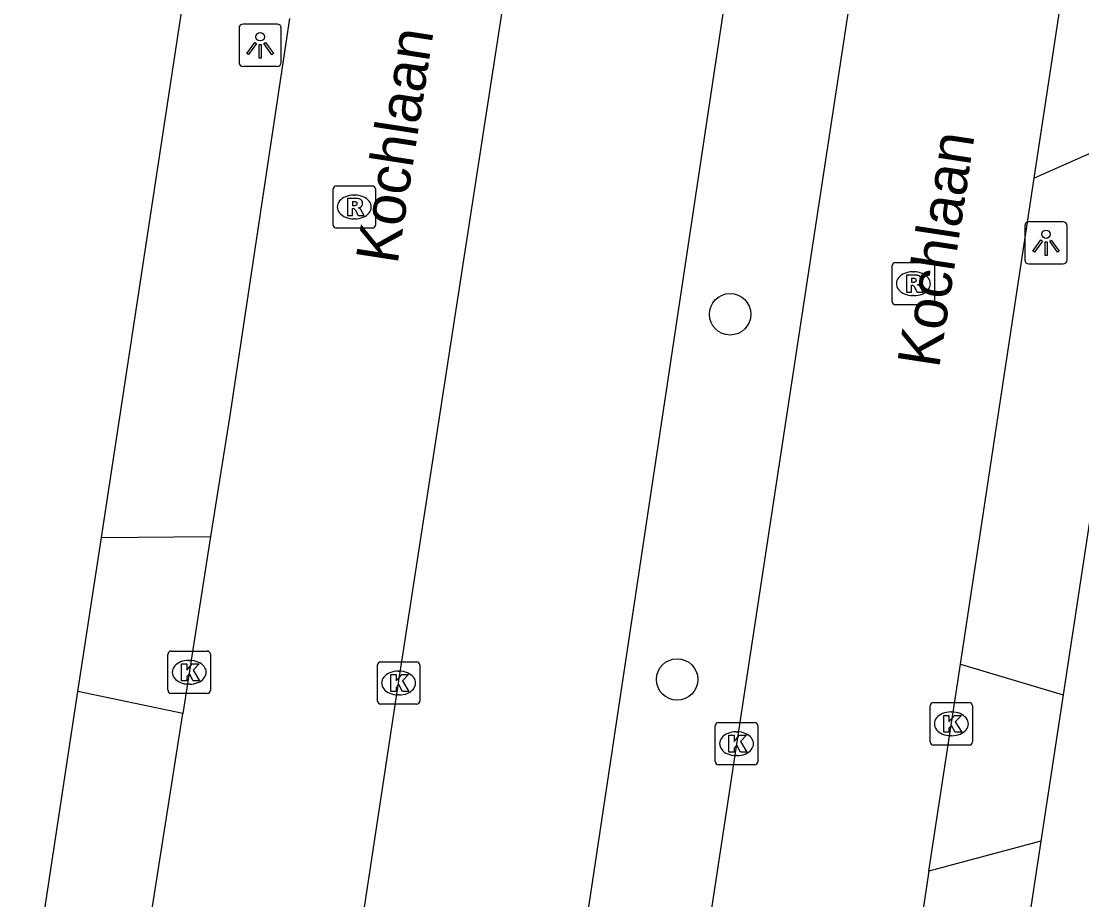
# Model space of a CAD drawing. Extents: x 161486 to 162249, y 379484 to 380829.
# Drawn here: x 161895.53 to 161920.56, y 380438.28 to 380459.01 of the extents above; entities that cross this region are included whole.
import ezdxf

# ---------------------------------------------------------------- set-up
doc = ezdxf.new("R2010")
doc.units = 0
for name, color, linetype in [('IMGEO_Boom', 7, 'Continuous'), ('IMGEO_Groenvoorziening', 7, 'Continuous'), ('IMGEO_Kolk', 7, 'Continuous'), ('IMGEO_Lichtpunt', 7, 'Continuous'), ('IMGEO_Openbare_ruimte_label', 7, 'Continuous'), ('IMGEO_Rijbaan_lokaal_open', 7, 'Continuous'), ('IMGEO_Rioolput', 7, 'Continuous'), ('IMGEO_Voetpad_open', 7, 'Continuous')]:
    doc.layers.add(name, color=color, linetype=linetype)

msp = doc.modelspace()

# ---------------------------------------------------------------- linework, layer by layer
at = {"layer": 'IMGEO_Boom'}
for centre in [(161912.261, 380452.096), (161911.009, 380443.48)]:
    msp.add_circle(centre, 0.489, dxfattribs=at)
at = {"layer": 'IMGEO_Groenvoorziening'}
msp.add_lwpolyline([(161908.746, 380436.913), (161912.348, 380460.87)], dxfattribs=at)
at = {"layer": 'IMGEO_Kolk'}
for p, q in [((161898.991, 380443.224), (161898.991, 380444.076)), ((161899.066, 380444.15), (161899.918, 380444.15)), ((161899.992, 380444.076), (161899.992, 380443.224)), ((161899.479, 380443.93), (161899.504, 380443.93)), ((161903.934, 380442.97), (161903.934, 380443.822)), ((161904.009, 380443.896), (161904.861, 380443.896)), ((161904.935, 380443.822), (161904.935, 380442.97)), ((161904.422, 380443.676), (161904.447, 380443.676)), ((161899.502, 380443.37), (161899.477, 380443.37)), ((161899.918, 380443.15), (161899.066, 380443.15)), ((161904.445, 380443.116), (161904.42, 380443.116)), ((161904.861, 380442.896), (161904.009, 380442.896)), ((161916.982, 380442.007), (161916.982, 380442.859)), ((161917.057, 380442.933), (161917.909, 380442.933)), ((161917.983, 380442.859), (161917.983, 380442.007)), ((161917.47, 380442.713), (161917.495, 380442.713)), ((161911.911, 380441.538), (161911.911, 380442.39)), ((161911.986, 380442.464), (161912.838, 380442.464)), ((161912.912, 380442.39), (161912.912, 380441.538)), ((161912.399, 380442.244), (161912.424, 380442.244)), ((161917.493, 380442.153), (161917.468, 380442.153)), ((161917.909, 380441.933), (161917.057, 380441.933)), ((161912.422, 380441.684), (161912.397, 380441.684)), ((161912.838, 380441.464), (161911.986, 380441.464))]:
    msp.add_line(p, q, dxfattribs=at)
for points in [[(161898.991, 380443.224), (161898.991, 380444.076)], [(161899.066, 380444.15), (161899.918, 380444.15)], [(161899.992, 380444.076), (161899.992, 380443.224)], [(161899.312, 380443.85), (161899.435, 380443.85), (161899.435, 380443.699), (161899.565, 380443.85), (161899.729, 380443.85), (161899.583, 380443.699), (161899.736, 380443.45), (161899.584, 380443.45), (161899.499, 380443.614), (161899.435, 380443.547), (161899.435, 380443.45), (161899.312, 380443.45), (161899.312, 380443.85)], [(161903.934, 380442.97), (161903.934, 380443.822)], [(161904.009, 380443.896), (161904.861, 380443.896)], [(161904.935, 380443.822), (161904.935, 380442.97)], [(161904.255, 380443.596), (161904.378, 380443.596), (161904.378, 380443.445), (161904.508, 380443.596), (161904.672, 380443.596), (161904.526, 380443.445), (161904.679, 380443.196), (161904.527, 380443.196), (161904.442, 380443.36), (161904.378, 380443.293), (161904.378, 380443.196), (161904.255, 380443.196), (161904.255, 380443.596)], [(161899.918, 380443.15), (161899.066, 380443.15)], [(161904.861, 380442.896), (161904.009, 380442.896)], [(161916.982, 380442.007), (161916.982, 380442.859)], [(161917.057, 380442.933), (161917.909, 380442.933)], [(161917.983, 380442.859), (161917.983, 380442.007)], [(161917.303, 380442.633), (161917.426, 380442.633), (161917.426, 380442.482), (161917.556, 380442.633), (161917.72, 380442.633), (161917.574, 380442.482), (161917.727, 380442.233), (161917.575, 380442.233), (161917.49, 380442.397), (161917.426, 380442.33), (161917.426, 380442.233), (161917.303, 380442.233), (161917.303, 380442.633)], [(161911.911, 380441.538), (161911.911, 380442.39)], [(161911.986, 380442.464), (161912.838, 380442.464)], [(161912.912, 380442.39), (161912.912, 380441.538)], [(161912.232, 380442.164), (161912.355, 380442.164), (161912.355, 380442.013), (161912.485, 380442.164), (161912.649, 380442.164), (161912.503, 380442.013), (161912.656, 380441.764), (161912.504, 380441.764), (161912.419, 380441.928), (161912.355, 380441.861), (161912.355, 380441.764), (161912.232, 380441.764), (161912.232, 380442.164)], [(161917.909, 380441.933), (161917.057, 380441.933)], [(161912.838, 380441.464), (161911.986, 380441.464)]]:
    msp.add_lwpolyline(points, dxfattribs=at)
for centre, start, end in [((161899.068, 380444.074), 91.552, 178.448), ((161899.068, 380444.074), 91.552, 178.448), ((161899.916, 380444.074), 1.552, 88.448), ((161899.916, 380444.074), 1.552, 88.448), ((161904.011, 380443.82), 91.552, 178.448), ((161904.011, 380443.82), 91.552, 178.448), ((161904.859, 380443.82), 1.552, 88.448), ((161904.859, 380443.82), 1.552, 88.448), ((161899.068, 380443.226), 181.552, 268.448), ((161899.068, 380443.226), 181.552, 268.448), ((161899.916, 380443.226), 271.552, 358.448), ((161899.916, 380443.226), 271.552, 358.448), ((161904.011, 380442.972), 181.552, 268.448), ((161904.011, 380442.972), 181.552, 268.448), ((161904.859, 380442.972), 271.552, 358.448), ((161904.859, 380442.972), 271.552, 358.448), ((161917.059, 380442.857), 91.552, 178.448), ((161917.059, 380442.857), 91.552, 178.448), ((161917.907, 380442.857), 1.552, 88.448), ((161917.907, 380442.857), 1.552, 88.448), ((161911.988, 380442.388), 91.552, 178.448), ((161911.988, 380442.388), 91.552, 178.448), ((161912.836, 380442.388), 1.552, 88.448), ((161912.836, 380442.388), 1.552, 88.448), ((161917.059, 380442.009), 181.552, 268.448), ((161917.059, 380442.009), 181.552, 268.448), ((161917.907, 380442.009), 271.552, 358.448), ((161917.907, 380442.009), 271.552, 358.448), ((161911.988, 380441.54), 181.552, 268.448), ((161911.988, 380441.54), 181.552, 268.448), ((161912.836, 380441.54), 271.552, 358.448), ((161912.836, 380441.54), 271.552, 358.448)]:
    msp.add_arc(centre, 0.0765, start, end, dxfattribs=at)
for centre, major_axis, ratio, start_param, end_param in [((161899.478, 380443.65), (-0.387, 0.002), 0.722429, 4.712389, 7.853982), ((161899.503, 380443.65), (-0.39, 0.002), 0.717154, 1.570796, 4.712389), ((161904.421, 380443.396), (-0.387, 0.002), 0.722429, 4.712389, 7.853982), ((161904.446, 380443.396), (-0.39, 0.002), 0.717154, 1.570796, 4.712389), ((161917.469, 380442.433), (-0.387, 0.002), 0.722429, 4.712389, 7.853982), ((161917.494, 380442.433), (-0.39, 0.002), 0.717154, 1.570796, 4.712389), ((161912.398, 380441.964), (-0.387, 0.002), 0.722429, 4.712389, 7.853982), ((161912.423, 380441.964), (-0.39, 0.002), 0.717154, 1.570796, 4.712389)]:
    msp.add_ellipse(centre, major_axis=major_axis, ratio=ratio, start_param=start_param, end_param=end_param, dxfattribs=at)
at = {"layer": 'IMGEO_Lichtpunt'}
for p, q in [((161900.668, 380458.848), (161900.668, 380458.041)), ((161900.668, 380458.848), (161900.668, 380458.041)), ((161901.57, 380458.943), (161900.762, 380458.943)), ((161901.57, 380458.943), (161900.762, 380458.943)), ((161901.664, 380458.041), (161901.664, 380458.848)), ((161901.664, 380458.041), (161901.664, 380458.848)), ((161900.762, 380457.947), (161901.57, 380457.947)), ((161900.762, 380457.947), (161901.57, 380457.947)), ((161919.218, 380454.186), (161919.218, 380453.379)), ((161919.218, 380454.186), (161919.218, 380453.379)), ((161920.12, 380454.281), (161919.312, 380454.281)), ((161920.12, 380454.281), (161919.312, 380454.281)), ((161920.214, 380453.379), (161920.214, 380454.186)), ((161920.214, 380453.379), (161920.214, 380454.186)), ((161919.312, 380453.285), (161920.12, 380453.285)), ((161919.312, 380453.285), (161920.12, 380453.285))]:
    msp.add_line(p, q, dxfattribs=at)
for points in [[(161901.042, 380458.512), (161901.081, 380458.484), (161900.893, 380458.222), (161900.855, 380458.249), (161901.042, 380458.512)], [(161901.144, 380458.464), (161901.191, 380458.464), (161901.191, 380458.142), (161901.144, 380458.142), (161901.144, 380458.464)], [(161901.254, 380458.484), (161901.292, 380458.511), (161901.479, 380458.249), (161901.44, 380458.221), (161901.254, 380458.484)], [(161919.592, 380453.85), (161919.631, 380453.822), (161919.443, 380453.56), (161919.405, 380453.587), (161919.592, 380453.85)], [(161919.804, 380453.822), (161919.842, 380453.849), (161920.029, 380453.587), (161919.99, 380453.559), (161919.804, 380453.822)], [(161919.694, 380453.802), (161919.741, 380453.802), (161919.741, 380453.48), (161919.694, 380453.48), (161919.694, 380453.802)]]:
    msp.add_lwpolyline(points, dxfattribs=at)
for centre in [(161901.167, 380458.646), (161919.717, 380453.984)]:
    msp.add_circle(centre, 0.0994, dxfattribs=at)
for centre, start, end in [((161900.762, 380458.848), 90, 180), ((161900.762, 380458.848), 90, 180), ((161901.57, 380458.848), 0, 90), ((161901.57, 380458.848), 0, 90), ((161900.762, 380458.041), 180, 270), ((161900.762, 380458.041), 180, 270), ((161901.57, 380458.041), 270, 0), ((161901.57, 380458.041), 270, 360), ((161919.312, 380454.186), 90, 180), ((161919.312, 380454.186), 90, 180), ((161920.12, 380454.186), 0, 90), ((161920.12, 380454.186), 0, 90), ((161919.312, 380453.379), 180, 270), ((161919.312, 380453.379), 180, 270), ((161920.12, 380453.379), 270, 0), ((161920.12, 380453.379), 270, 360)]:
    msp.add_arc(centre, 0.0946, start, end, dxfattribs=at)
at = {"layer": 'IMGEO_Rijbaan_lokaal_open'}
for points in [[(161916.269, 380467.244), (161913.458, 380448.83), (161909.61, 380423.559), (161908.667, 380417.626)], [(161919.434, 380455.31), (161920.58, 380462.821)], [(161903.567, 380437.693), (161904.441, 380443.444), (161907.235, 380461.539)], [(161901.858, 380459.079), (161900.447, 380449.706), (161899.998, 380446.856)], [(161917.695, 380443.841), (161919.434, 380455.31)], [(161899.998, 380446.856), (161899.34, 380442.677)], [(161916.954, 380438.957), (161917.695, 380443.841)], [(161895.846, 380420.471), (161896.125, 380421.511), (161896.176, 380421.7), (161896.34, 380422.706), (161896.517, 380424.014), (161898.386, 380436.621), (161899.34, 380442.677)], [(161916.954, 380438.957), (161916.279, 380434.508), (161913.944, 380419.175), (161913.655, 380417.428)]]:
    msp.add_lwpolyline(points, dxfattribs=at)
at = {"layer": 'IMGEO_Rioolput'}
for p, q in [((161902.963, 380455.128), (161903.815, 380455.128)), ((161902.888, 380454.202), (161902.888, 380455.054)), ((161903.376, 380454.908), (161903.401, 380454.908)), ((161903.889, 380455.054), (161903.889, 380454.202)), ((161903.399, 380454.348), (161903.374, 380454.348)), ((161903.815, 380454.128), (161902.963, 380454.128)), ((161916.16, 380453.318), (161917.012, 380453.318)), ((161916.085, 380452.392), (161916.085, 380453.244)), ((161916.573, 380453.098), (161916.598, 380453.098)), ((161917.086, 380453.244), (161917.086, 380452.392)), ((161917.012, 380452.318), (161916.16, 380452.318)), ((161916.596, 380452.538), (161916.571, 380452.538))]:
    msp.add_line(p, q, dxfattribs=at)
for points in [[(161902.963, 380455.128), (161903.815, 380455.128)], [(161902.888, 380454.202), (161902.888, 380455.054)], [(161903.477, 380454.826), (161903.225, 380454.828), (161903.225, 380454.428)], [(161903.889, 380455.054), (161903.889, 380454.202)], [(161903.225, 380454.428), (161903.349, 380454.428), (161903.349, 380454.59), (161903.36, 380454.59)], [(161903.403, 380454.747), (161903.349, 380454.747), (161903.349, 380454.666)], [(161903.349, 380454.666), (161903.401, 380454.666)], [(161903.407, 380454.561), (161903.478, 380454.428), (161903.618, 380454.428), (161903.553, 380454.554)], [(161903.815, 380454.128), (161902.963, 380454.128)], [(161916.16, 380453.318), (161917.012, 380453.318)], [(161916.085, 380452.392), (161916.085, 380453.244)], [(161917.086, 380453.244), (161917.086, 380452.392)], [(161916.674, 380453.016), (161916.422, 380453.018), (161916.422, 380452.618)], [(161916.6, 380452.937), (161916.546, 380452.937), (161916.546, 380452.856)], [(161916.546, 380452.856), (161916.598, 380452.856)], [(161916.422, 380452.618), (161916.546, 380452.618), (161916.546, 380452.78), (161916.557, 380452.78)], [(161916.604, 380452.751), (161916.675, 380452.618), (161916.815, 380452.618), (161916.75, 380452.744)], [(161917.012, 380452.318), (161916.16, 380452.318)]]:
    msp.add_lwpolyline(points, dxfattribs=at)
for centre, radius, start, end in [((161902.965, 380455.052), 0.0765, 91.552, 178.448), ((161902.965, 380455.052), 0.0765, 91.552, 178.448), ((161903.813, 380455.052), 0.0765, 1.552, 88.448), ((161903.813, 380455.052), 0.0765, 1.552, 88.448), ((161903.476, 380454.716), 0.109, 350.3612, 89.416), ((161903.359, 380454.537), 0.0533, 26.0293, 88.6989), ((161903.385, 380454.855), 0.19, 274.7715, 282.9687), ((161903.409, 380454.651), 0.0964, 77.0061, 93.1865), ((161903.423, 380454.708), 0.0378, 276.6634, 79.6772), ((161903.474, 380454.716), 0.112, 277.5842, 350.9817), ((161903.458, 380454.501), 0.108, 29.5134, 73.7905), ((161902.965, 380454.204), 0.0765, 181.552, 268.448), ((161902.965, 380454.204), 0.0765, 181.552, 268.448), ((161903.813, 380454.204), 0.0765, 271.552, 358.448), ((161903.813, 380454.204), 0.0765, 271.552, 358.448), ((161916.162, 380453.242), 0.0765, 91.552, 178.448), ((161916.162, 380453.242), 0.0765, 91.552, 178.448), ((161917.01, 380453.242), 0.0765, 1.552, 88.448), ((161917.01, 380453.242), 0.0765, 1.552, 88.448), ((161916.582, 380453.045), 0.19, 274.7715, 282.9687), ((161916.606, 380452.841), 0.0964, 77.0061, 93.1865), ((161916.62, 380452.898), 0.0378, 276.6634, 79.6772), ((161916.673, 380452.906), 0.109, 350.3612, 89.416), ((161916.671, 380452.906), 0.112, 277.5842, 350.9817), ((161916.556, 380452.727), 0.0533, 26.0293, 88.6989), ((161916.655, 380452.691), 0.108, 29.5134, 73.7905), ((161916.162, 380452.394), 0.0765, 181.552, 268.448), ((161916.162, 380452.394), 0.0765, 181.552, 268.448), ((161917.01, 380452.394), 0.0765, 271.552, 358.448), ((161917.01, 380452.394), 0.0765, 271.552, 358.448)]:
    msp.add_arc(centre, radius, start, end, dxfattribs=at)
for centre, major_axis, ratio, start_param, end_param in [((161903.375, 380454.628), (-0.387, 0.002), 0.722429, 4.712389, 7.853982), ((161903.4, 380454.628), (-0.39, 0.002), 0.717154, 1.570796, 4.712389), ((161916.572, 380452.818), (-0.387, 0.002), 0.722429, 4.712389, 7.853982), ((161916.597, 380452.818), (-0.39, 0.002), 0.717154, 1.570796, 4.712389)]:
    msp.add_ellipse(centre, major_axis=major_axis, ratio=ratio, start_param=start_param, end_param=end_param, dxfattribs=at)
at = {"layer": 'IMGEO_Voetpad_open'}
for points in [[(161897.419, 380446.831), (161899.426, 380460.006)], [(161922.159, 380456.515), (161919.434, 380455.31)], [(161922.159, 380456.515), (161920.124, 380443.114)], [(161896.865, 380443.194), (161897.419, 380446.831)], [(161897.419, 380446.831), (161899.998, 380446.856)], [(161917.695, 380443.841), (161920.124, 380443.114)], [(161893.668, 380422.201), (161896.865, 380443.194)], [(161899.34, 380442.677), (161896.865, 380443.194)], [(161920.124, 380443.114), (161919.599, 380439.661)], [(161919.599, 380439.661), (161916.152, 380416.963)], [(161919.599, 380439.661), (161916.954, 380438.957)]]:
    msp.add_lwpolyline(points, dxfattribs=at)

# ---------------------------------------------------------------- texts
at = {"layer": 'IMGEO_Openbare_ruimte_label'}
for rotation, p in [(81.1972, (161904.408, 380453.256)), (81.3191, (161917.192, 380450.804))]:
    msp.add_text('Kochlaan', height=1, rotation=rotation, dxfattribs=at).set_placement(p)

doc.saveas('drawing.dxf')
